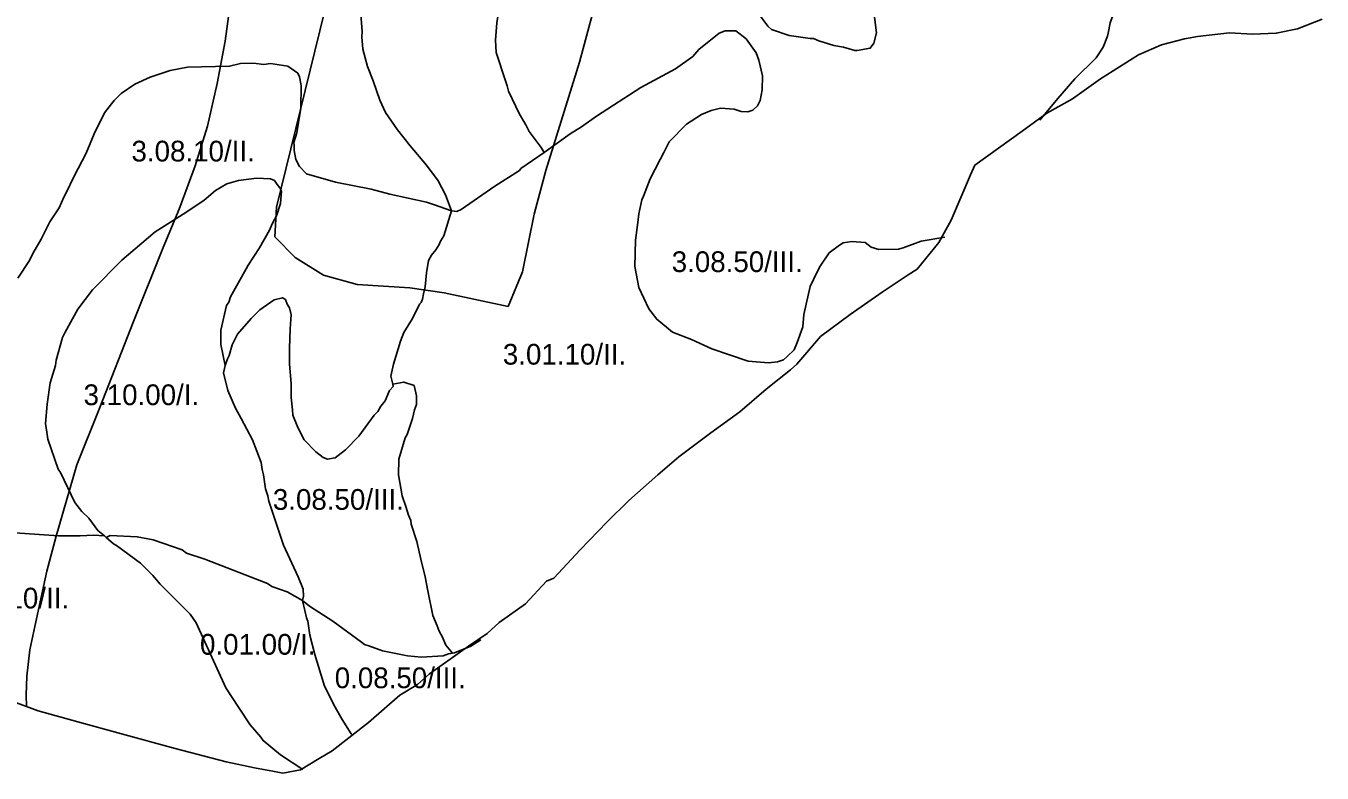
# Model space of a CAD drawing. Extents: x -555509 to -553014, y -1186753 to -1182560.
# Drawn here: x -554443 to -553192, y -1186753 to -1186033 of the extents above; entities that cross this region are included whole.
import ezdxf

# ---------------------------------------------------------------- set-up
doc = ezdxf.new("R2010")
doc.units = 0
for name, color, linetype in [('Level 29', 7, 'Continuous'), ('Level 41', 7, 'Continuous'), ('pěší_tr', 7, 'Continuous')]:
    doc.layers.add(name, color=color, linetype=linetype)

msp = doc.modelspace()

# ---------------------------------------------------------------- linework, layer by layer
at = {"layer": 'Level 29'}
for points in [[(-553597, -1185943.2), (-553583.9, -1185954.4), (-553577.5, -1185956.9), (-553558.4, -1185961.5), (-553533.9, -1185962.4), (-553521.6, -1185960.8), (-553473.6, -1185960.2), (-553441.4, -1185969.1), (-553410.9, -1185988.2), (-553402.4, -1185996.8), (-553396.9, -1185999.3), (-553394.4, -1186012.4), (-553393.9, -1186022.6), (-553396.5, -1186029.4), (-553398.6, -1186039.5), (-553399, -1186042.5), (-553403.2, -1186053.1), (-553410.1, -1186063.3), (-553430.8, -1186083.6), (-553447.2, -1186102.6), (-553464.4, -1186123.4)], [(-553942.6, -1186154.5), (-553945.5, -1186149.8), (-553957, -1186134.5), (-553960.4, -1186127.8), (-553966.3, -1186117.6), (-553976.9, -1186095.5), (-553978.2, -1186090.4), (-553979.9, -1186085.4), (-553988.8, -1186058.2), (-553989.6, -1186046.4), (-553988.4, -1186029.4), (-553984.9, -1186007.4), (-553982.4, -1185999.8), (-553982, -1185994.6), (-553977.8, -1185986.1), (-553966.3, -1185962.4), (-553962.9, -1185950.1)], [(-554120.2, -1186012.9), (-554118.1, -1186037.9), (-554118.5, -1186043), (-554117.7, -1186054.9), (-554113, -1186071.8), (-554107.5, -1186085.4), (-554101.1, -1186104), (-554095.6, -1186115.9), (-554084.2, -1186132.9), (-554071.9, -1186148.1), (-554056.2, -1186166.8), (-554044.8, -1186182), (-554037.9, -1186195.6), (-554032, -1186210.9)], [(-553624.6, -1186018.8), (-553622.1, -1186039.1), (-553624.6, -1186049.2), (-553628, -1186054), (-553640.7, -1186056.1), (-553642.8, -1186056.1), (-553653.8, -1186053.1), (-553663.2, -1186051.4), (-553677.6, -1186046.8), (-553682.7, -1186044.6), (-553686.1, -1186044.6), (-553706.4, -1186041.6), (-553723.4, -1186036.1), (-553726.8, -1186032.8), (-553736.9, -1186019.3)], [(-553942.6, -1186154.5), (-553917.6, -1186136.6), (-553906.5, -1186129.9), (-553892.1, -1186119.6), (-553849.3, -1186091.8), (-553815.8, -1186073.9), (-553799.2, -1186062), (-553793.3, -1186055.3), (-553773.8, -1186039.5), (-553767.9, -1186037.4), (-553757.7, -1186037.4), (-553747.9, -1186045.1), (-553738.2, -1186058.6), (-553735.7, -1186065.4), (-553731.9, -1186080.6), (-553732.2, -1186094.2), (-553734.4, -1186104.4), (-553736.9, -1186109.5), (-553741.2, -1186113.8), (-553746.2, -1186115.5), (-553752.6, -1186115), (-553759.4, -1186112.9), (-553772.6, -1186112), (-553781.4, -1186114.1), (-553790.8, -1186118), (-553805.2, -1186127.4), (-553822.1, -1186144.3), (-553827.2, -1186154.5), (-553830.6, -1186161.3), (-553840.4, -1186179.9), (-553846.8, -1186196.9), (-553848.4, -1186200.3), (-553851.4, -1186213.8), (-553852.2, -1186222.3), (-553854.4, -1186239.2), (-553855.2, -1186264.6), (-553851.4, -1186285), (-553841.6, -1186305.4), (-553834, -1186315.5), (-553818.8, -1186327.9), (-553800.5, -1186335.1), (-553781, -1186344), (-553745.8, -1186355.9), (-553726.3, -1186357.5), (-553717.4, -1186356.6), (-553711.9, -1186354.6), (-553708.1, -1186351.6), (-553701.3, -1186344.9), (-553698.4, -1186338), (-553693.2, -1186322.8), (-553692, -1186310.9), (-553686.1, -1186283.8), (-553679.7, -1186270.3), (-553676.3, -1186264.2), (-553667.8, -1186251.5), (-553657.6, -1186243.9), (-553654.2, -1186241.8), (-553645.8, -1186240.5), (-553633.1, -1186241.4), (-553627.1, -1186246), (-553619.9, -1186248.1), (-553600.8, -1186247.8), (-553596.2, -1186246.5), (-553578.8, -1186240.1), (-553556.1, -1186236.2)], [(-554450.5, -1186275.8), (-554439.1, -1186258.8), (-554436.1, -1186252), (-554428, -1186238.4), (-554419.6, -1186221.5), (-554410.6, -1186207.9), (-554406, -1186197.8), (-554404.2, -1186194.2), (-554396.2, -1186177.4), (-554384.4, -1186155.2), (-554376.7, -1186136.6), (-554366.9, -1186116.3), (-554360.2, -1186107.8), (-554357.6, -1186104.4), (-554350.9, -1186097.6), (-554337.7, -1186088.8), (-554322.9, -1186082), (-554303.4, -1186075.6), (-554286.8, -1186072.3), (-554246.1, -1186071.4), (-554235.5, -1186068.8), (-554223.2, -1186068.4), (-554213.1, -1186069.6), (-554206.7, -1186068.8), (-554189.8, -1186071.4), (-554180.4, -1186078.1), (-554178.7, -1186081.5), (-554177, -1186090), (-554177.4, -1186112), (-554179.6, -1186125.6), (-554181.2, -1186135.8), (-554184.2, -1186145.1), (-554183.8, -1186147.6), (-554183.8, -1186152.8), (-554182.1, -1186161.3), (-554178.7, -1186168), (-554171.9, -1186175.2), (-554143.9, -1186183.2), (-554109.6, -1186190.1), (-554091.4, -1186194.8), (-554056.2, -1186202.4), (-554049.4, -1186204.9), (-554032, -1186210.9)], [(-554032, -1186210.9), (-554026.9, -1186211.6), (-554022.7, -1186209.6), (-553990.1, -1186187.1), (-553966.3, -1186171.9), (-553965.1, -1186170.1), (-553942.6, -1186154.5)], [(-554366.9, -1186524.6), (-554373.3, -1186519.5), (-554381.8, -1186507.6), (-554388.6, -1186500.9), (-554395.4, -1186492.4), (-554409.4, -1186463.5), (-554411.5, -1186460.1), (-554421.6, -1186431.3), (-554422.5, -1186424.5), (-554423.8, -1186416), (-554422.1, -1186397.4), (-554419.1, -1186377), (-554414, -1186360.1), (-554413.6, -1186355), (-554407.2, -1186333), (-554404.7, -1186327.9), (-554392.4, -1186305.8), (-554378.4, -1186287.1), (-554350, -1186258.4), (-554317.8, -1186231.2), (-554288.5, -1186212.5), (-554270.8, -1186200.6), (-554259.7, -1186191.4), (-554248.7, -1186185), (-554237.6, -1186181.6), (-554220.2, -1186179.5), (-554206.7, -1186179.9), (-554202.9, -1186181.6), (-554200.3, -1186185.4), (-554197.8, -1186188.8), (-554196.1, -1186192.1), (-554196.9, -1186204), (-554200.8, -1186215.9), (-554204.6, -1186222.8), (-554207.6, -1186229.5), (-554217.3, -1186246.5), (-554228.3, -1186263.4), (-554230, -1186266.8), (-554245.2, -1186294), (-554247, -1186299), (-554249.1, -1186302.4), (-554254.6, -1186326.1), (-554254.6, -1186339.8), (-554250.3, -1186360.2)], [(-554088.8, -1186378.2), (-554090.5, -1186370.6), (-554088, -1186358.8), (-554081.2, -1186336.8), (-554078.2, -1186328.2), (-554069.8, -1186314.8), (-554063, -1186301.1), (-554061.2, -1186299.5), (-554060, -1186296), (-554059.1, -1186291), (-554057.4, -1186284.1), (-554056.2, -1186270.6), (-554054.1, -1186258.8), (-554051.5, -1186253.6), (-554047.3, -1186248.6), (-554043.9, -1186243.5), (-554042.6, -1186240.1), (-554039.6, -1186235), (-554032, -1186210.9)], [(-554250.3, -1186360.2), (-554248.2, -1186353.8), (-554246.6, -1186350.4), (-554243.6, -1186340.1), (-554238.5, -1186330), (-554225.4, -1186314.8), (-554216.9, -1186306.3), (-554203.3, -1186296.9), (-554195.2, -1186294.8), (-554192.1, -1186296.5), (-554190.6, -1186301.1), (-554188.5, -1186304.5), (-554186.8, -1186311.4), (-554187.6, -1186324.9), (-554188.5, -1186343.5), (-554188.5, -1186352), (-554188.5, -1186358.8), (-554186.8, -1186377.5), (-554186.8, -1186391), (-554185.5, -1186402.9), (-554185.1, -1186408), (-554180.4, -1186419.9), (-554174.1, -1186431.8), (-554163, -1186443.6), (-554155.8, -1186448.8), (-554151.6, -1186450.4), (-554144.4, -1186449.1), (-554141.4, -1186447), (-554134.2, -1186441.5), (-554121.5, -1186428.4), (-554106.6, -1186408), (-554103.2, -1186404.6), (-554100.2, -1186399.5), (-554096.1, -1186394.4), (-554091.8, -1186384.3), (-554088.4, -1186380.4), (-554088.8, -1186378.2)], [(-554250.3, -1186360.2), (-554251.2, -1186363), (-554252.1, -1186367.3), (-554247.8, -1186384.3), (-554240.6, -1186401.2), (-554235.1, -1186411.4), (-554224.1, -1186431.8), (-554215.6, -1186453.8), (-554214.8, -1186460.5), (-554213.5, -1186465.6), (-554211.4, -1186479.2), (-554209.2, -1186486), (-554208.4, -1186491.1), (-554194, -1186533.5), (-554180, -1186564), (-554175.3, -1186575.9), (-554174.9, -1186582.6), (-554175.8, -1186586.9)], [(-554088.8, -1186378.2), (-554078.2, -1186376.2), (-554068.1, -1186379.6), (-554065.9, -1186389.4), (-554065.9, -1186397.8), (-554067.6, -1186402.9), (-554069.8, -1186411.4), (-554074.8, -1186426.6), (-554076.9, -1186430), (-554082.9, -1186450.4), (-554083.3, -1186465.6), (-554079.5, -1186486), (-554076.1, -1186496.1), (-554073.6, -1186504.6), (-554071.4, -1186509.8), (-554071, -1186513.1), (-554065.5, -1186530.1), (-554061.7, -1186547), (-554057.4, -1186564), (-554054.9, -1186577.6), (-554050.2, -1186601.4), (-554046, -1186611.5), (-554043.9, -1186616.6), (-554040.9, -1186621.6), (-554037.6, -1186630.1), (-554031.2, -1186637.8)], [(-554643.8, -1186442.4), (-554631.5, -1186459.8), (-554617.6, -1186471.6), (-554610.8, -1186475.9), (-554573.9, -1186495.4), (-554538.2, -1186510.1), (-554515.8, -1186517), (-554492.1, -1186519.9), (-554453, -1186521.6), (-554411.1, -1186524.6), (-554390.2, -1186524.6), (-554377.6, -1186523.8), (-554366.9, -1186524.6)], [(-554365.3, -1186526), (-554366.9, -1186524.6)], [(-554175.8, -1186586.9), (-554190.6, -1186578.4), (-554205.4, -1186573.4), (-554209.7, -1186570.4), (-554269.9, -1186547), (-554287.7, -1186541.1), (-554291.9, -1186538.1), (-554319.9, -1186528.4), (-554335.2, -1186525.4), (-554361.4, -1186524.1), (-554365.3, -1186526)], [(-554365.3, -1186526), (-554358.1, -1186532.3), (-554355.1, -1186533.9), (-554332.2, -1186550.9), (-554320.3, -1186562.8), (-554313.1, -1186571.2), (-554284.3, -1186600), (-554278.4, -1186608.5), (-554249.9, -1186671.3), (-554237.6, -1186689.9), (-554226.2, -1186706.9), (-554216, -1186718.8), (-554213.9, -1186722.1), (-554196.9, -1186735.8), (-554175.5, -1186749.9)], [(-554175.8, -1186586.9), (-554168.9, -1186592.4), (-554146.5, -1186606.9), (-554118.9, -1186627.1), (-554116, -1186629.2), (-554111.8, -1186630.6), (-554098.6, -1186635.6), (-554074.4, -1186640.4), (-554060.9, -1186641.6), (-554040.1, -1186640.4), (-554035, -1186638.3), (-554031.2, -1186637.8)], [(-554127.1, -1186717.2), (-554128.7, -1186715.4), (-554137.6, -1186701.8), (-554144.4, -1186689.9), (-554154.6, -1186669.6), (-554163.9, -1186639), (-554168.6, -1186620.4), (-554170.7, -1186606.9), (-554171.9, -1186603.5), (-554173.6, -1186596.6), (-554175.8, -1186586.9)], [(-554003.7, -1186624.9), (-554013.4, -1186631), (-554029.1, -1186637.4), (-554031.2, -1186637.8)]]:
    msp.add_lwpolyline(points, dxfattribs=at)
at = {"layer": 'Level 41'}
for points in [[(-554183, -1186256.1), (-554155.5, -1186273.1), (-554123.1, -1186282), (-554072.1, -1186285.2), (-554039, -1186290.1), (-553977.5, -1186303.1), (-553963.7, -1186269.9), (-553952.4, -1186214), (-553941.1, -1186171.9), (-553908.7, -1186067.5), (-553889.3, -1185995.5), (-553903, -1185979.3), (-553917.6, -1185938.8), (-553935.4, -1185878.1), (-553960.5, -1185832.8), (-553991.2, -1185806.9), (-554024.4, -1185792.3), (-554056, -1185797.1), (-554144.1, -1185805.2), (-554079.4, -1185868.4), (-554119.9, -1185882.1), (-554123.1, -1185894.3), (-554154.7, -1186018.9), (-554200.8, -1186207.5)], [(-554200.8, -1186207.5), (-554202.4, -1186235.9), (-554183, -1186256.1)]]:
    msp.add_lwpolyline(points, dxfattribs=at)
at = {"layer": 'pěší_tr'}
for points in [[(-554245.7, -1186011.5), (-554250.4, -1186047.3), (-554258, -1186087.9), (-554267.5, -1186129.2), (-554279.2, -1186167.4), (-554294.8, -1186209.3), (-554310.1, -1186246.3), (-554338.9, -1186317.8), (-554371.4, -1186400.8), (-554393.5, -1186455.9), (-554413.5, -1186524.7), (-554422.5, -1186558.5), (-554434.1, -1186611.9), (-554438.9, -1186634.6), (-554441.8, -1186659.8), (-554442.3, -1186678.4), (-554442.2, -1186689.1)], [(-554451.7, -1186685.7), (-554430.7, -1186693.2), (-554392.7, -1186704), (-554350.5, -1186715.6), (-554298.5, -1186729.6), (-554249.3, -1186742.5), (-554222.1, -1186748.3), (-554202.9, -1186752), (-554194.7, -1186753.4), (-554177.7, -1186750.3), (-554159.8, -1186739.2), (-554147.3, -1186731.8), (-554112.1, -1186704.6), (-554082, -1186678.3), (-554064.9, -1186667.8), (-554053.4, -1186657.8), (-554015.7, -1186631.1), (-553997.5, -1186618.7), (-553986.2, -1186608.2), (-553960.8, -1186590.2), (-553940.3, -1186568.1), (-553933.3, -1186565.2), (-553907.8, -1186538.1), (-553882, -1186511), (-553860.9, -1186490.3), (-553833.1, -1186465.7), (-553812.6, -1186448.4), (-553781.7, -1186425.2), (-553753.8, -1186404.8), (-553728.5, -1186383.1), (-553704.9, -1186364.4), (-553698.8, -1186358.8), (-553676.2, -1186332.3), (-553647.5, -1186310.9), (-553616.5, -1186289.3), (-553591.4, -1186272.7), (-553582.9, -1186267.2), (-553561.9, -1186241.4), (-553550, -1186219.9), (-553531.4, -1186176.3), (-553527, -1186167), (-553481.6, -1186134), (-553457.8, -1186116.7), (-553432.8, -1186102.7), (-553405.9, -1186083.4), (-553369.4, -1186060.3), (-553347, -1186050.9), (-553325, -1186045.1), (-553312.3, -1186042.7), (-553281.4, -1186039.1), (-553259.3, -1186040.5), (-553236.3, -1186039.5), (-553215.9, -1186035.2), (-553192.1, -1186026)]]:
    msp.add_lwpolyline(points, dxfattribs=at)

# ---------------------------------------------------------------- texts
at = {"layer": 'Level 29'}
for s, p in [('3.08.10/II.', (-554340.8, -1186163.3)), ('3.08.50/III.', (-553819.6, -1186270)), ('3.01.10/II.', (-553982.5, -1186359.3)), ('3.10.00/I.', (-554387, -1186398.4)), ('3.08.50/III.', (-554204.4, -1186499.4)), ('0.08.10/II.', (-554519.9, -1186594.6)), ('0.01.00/I.', (-554274.7, -1186639.2)), ('0.08.50/III.', (-554144.7, -1186671.5))]:
    msp.add_text(s, height=20, dxfattribs=at).set_placement(p)

doc.saveas('drawing.dxf')
